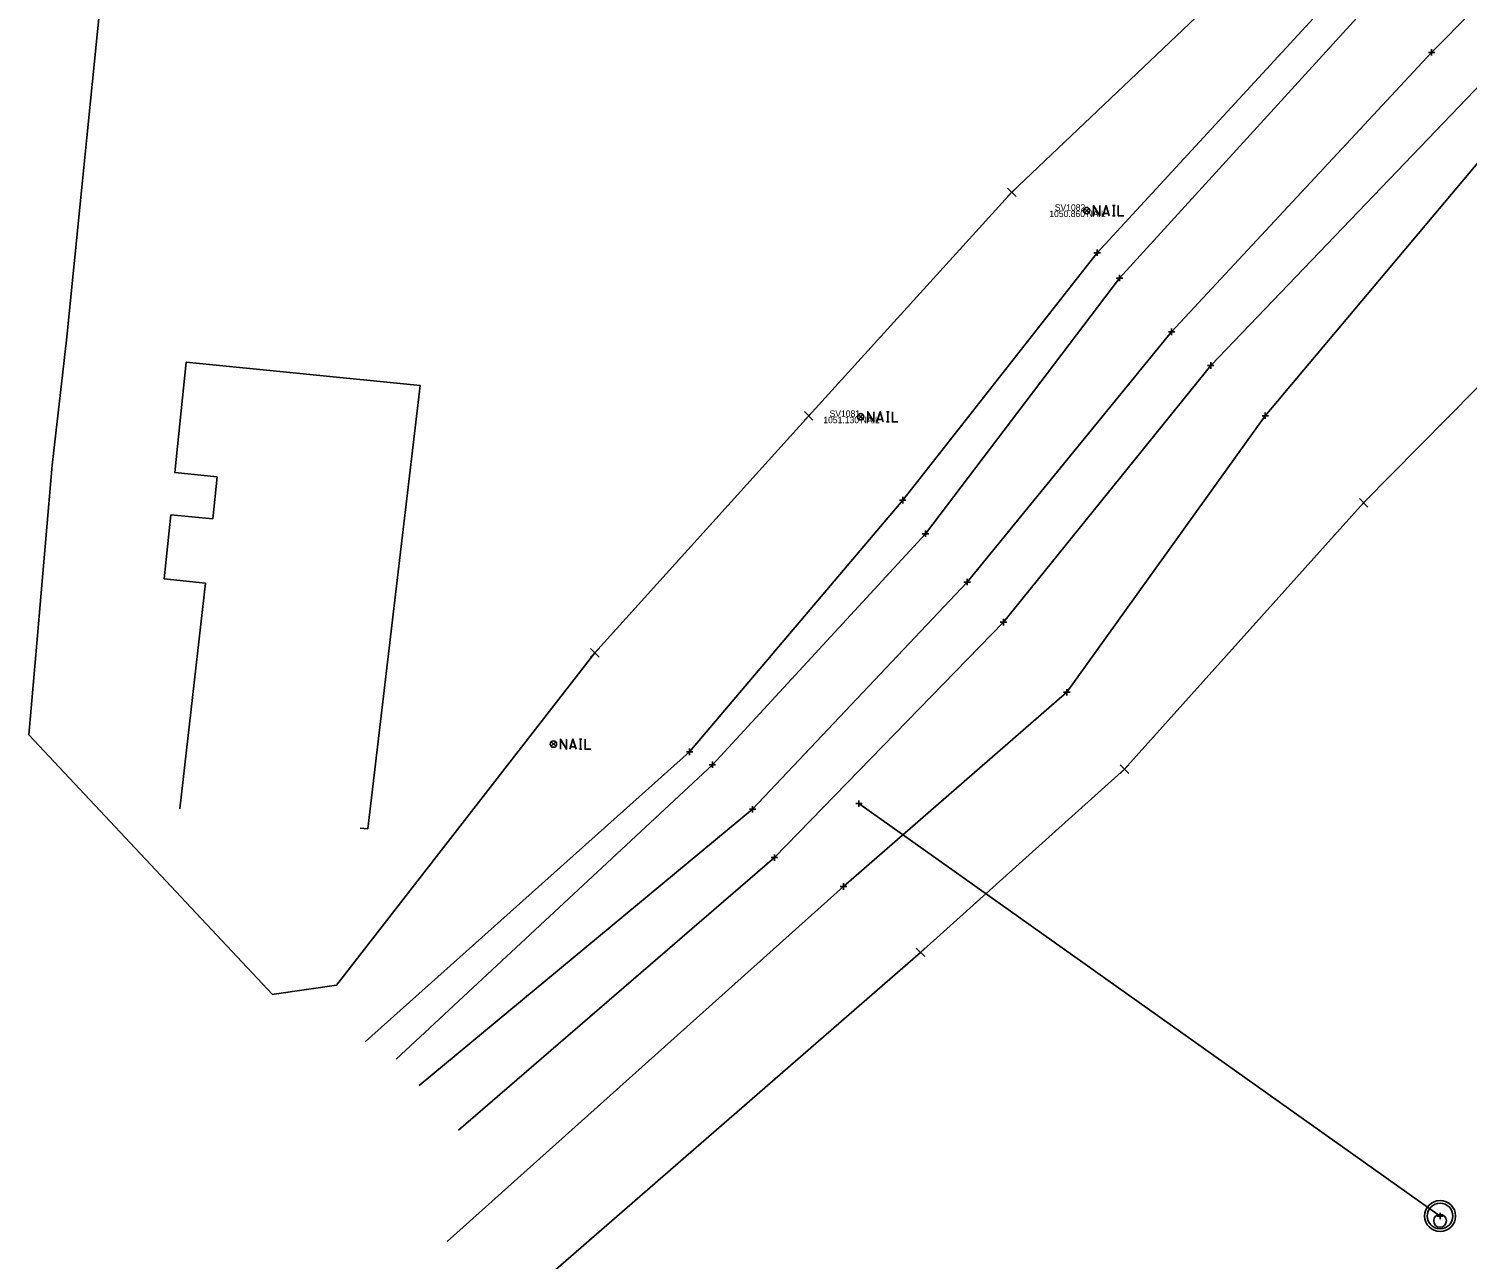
# Model space of a CAD drawing. Extents: x 1620404 to 1621386, y 607070 to 607748.
# Drawn here: x 1620985.2 to 1621209.9, y 607390.4 to 607582.5 of the extents above; entities that cross this region are included whole.
import ezdxf

# ---------------------------------------------------------------- set-up
doc = ezdxf.new("R2010")
doc.units = 0
for name, color, linetype in [('BD_X_Building', 7, 'Continuous'), ('BD_X_Porch_or_Deck', 7, 'Continuous'), ('Default', 7, 'Continuous'), ('DR_X_Cells', 7, 'Continuous'), ('DR_X_Elev_Flow', 7, 'Continuous'), ('PM_X_Cells', 7, 'Continuous'), ('PV_X_Curb', 7, 'Continuous'), ('SN_X_Public', 7, 'Continuous'), ('SV_P_Control_Cells_Set', 7, 'Continuous'), ('SV_X_Shot_Marker', 7, 'Continuous'), ('UT_X_Gas_Cells', 7, 'Continuous'), ('UT_X_Sanitary_Cells', 7, 'Continuous'), ('UT_X_Sanitary_Line', 7, 'Continuous'), ('UT_X_Water', 7, 'Continuous'), ('UT_X_Water_Cells', 7, 'Continuous'), ('VG_X_Cells', 7, 'Continuous')]:
    doc.layers.add(name, color=color, linetype=linetype)

msp = doc.modelspace()

# ---------------------------------------------------------------- linework, layer by layer
at = {"layer": 'BD_X_Porch_or_Deck'}
msp.add_line((1621114.88, 607461.49), (1621205.63, 607397.11), dxfattribs=at)
at = {"layer": 'Default'}
for points in [[(1621181.91, 607597.97), (1621138.75, 607556.94), (1621107.03, 607522.04), (1621073.63, 607485.02), (1621033.29, 607433.17), (1621023.55, 607431.72), (1621023.3, 607431.68), (1620985.23, 607472.25), (1620986.35, 607484.73), (1620988.88, 607514.33), (1620991.13, 607533.86), (1620993.6, 607558.73), (1620994.28, 607565.51), (1620996.79, 607590.39)], [(1621054.39, 607377.32), (1621124.5, 607438.27), (1621156.33, 607466.87), (1621193.69, 607508.45), (1621263.9, 607579.48)]]:
    msp.add_lwpolyline(points, dxfattribs=at)
at = {"layer": 'DR_X_Cells'}
for p, q in [((1621114.38, 607461.49), (1621115.38, 607461.49)), ((1621114.88, 607461.99), (1621114.88, 607460.99)), ((1621114.88, 607461.49), (1621114.88, 607461.49)), ((1621205.13, 607397.11), (1621206.13, 607397.11)), ((1621205.63, 607397.61), (1621205.63, 607396.61)), ((1621205.63, 607397.11), (1621205.63, 607397.11))]:
    msp.add_line(p, q, dxfattribs=at)
at = {"layer": 'DR_X_Elev_Flow'}
for p, q in [((1621150.09, 607554.43), (1621150.79, 607553.73)), ((1621150.09, 607553.73), (1621150.79, 607554.43)), ((1621114.8, 607522.24), (1621115.5, 607521.54)), ((1621114.8, 607521.54), (1621115.5, 607522.24)), ((1621066.82, 607471.14), (1621067.52, 607470.44)), ((1621066.82, 607470.44), (1621067.52, 607471.14))]:
    msp.add_line(p, q, dxfattribs=at)
for points in [[(1621151.53, 607553.27), (1621151.53, 607554.87), (1621152.47, 607553.27), (1621152.47, 607554.87)], [(1621152.98, 607553.27), (1621153.48, 607554.87), (1621153.97, 607553.27)], [(1621154.48, 607554.87), (1621154.88, 607554.87)], [(1621154.68, 607553.27), (1621154.68, 607554.87)], [(1621155.38, 607554.87), (1621155.38, 607553.27), (1621156.25, 607553.27)], [(1621153.85, 607553.65), (1621153.1, 607553.65)], [(1621154.48, 607553.27), (1621154.88, 607553.27)], [(1621116.24, 607521.08), (1621116.24, 607522.68), (1621117.18, 607521.08), (1621117.18, 607522.68)], [(1621117.69, 607521.08), (1621118.19, 607522.68), (1621118.68, 607521.08)], [(1621119.19, 607522.68), (1621119.59, 607522.68)], [(1621119.39, 607521.08), (1621119.39, 607522.68)], [(1621120.09, 607522.68), (1621120.09, 607521.08), (1621120.96, 607521.08)], [(1621118.56, 607521.46), (1621117.81, 607521.46)], [(1621119.19, 607521.08), (1621119.59, 607521.08)], [(1621068.26, 607469.98), (1621068.26, 607471.58), (1621069.2, 607469.98), (1621069.2, 607471.58)], [(1621069.71, 607469.98), (1621070.21, 607471.58), (1621070.7, 607469.98)], [(1621071.21, 607471.58), (1621071.61, 607471.58)], [(1621071.41, 607469.98), (1621071.41, 607471.58)], [(1621072.11, 607471.58), (1621072.11, 607469.98), (1621072.98, 607469.98)], [(1621070.58, 607470.36), (1621069.83, 607470.36)], [(1621071.21, 607469.98), (1621071.61, 607469.98)]]:
    msp.add_lwpolyline(points, dxfattribs=at)
for centre in [(1621150.44, 607554.08), (1621115.15, 607521.89), (1621067.17, 607470.79)]:
    msp.add_circle(centre, 0.5, dxfattribs=at)
at = {"layer": 'PM_X_Cells'}
for centre, radius in [((1621205.63, 607397.11), 2.42), ((1621205.63, 607397.11), 2), ((1621205.63, 607396.36), 1)]:
    msp.add_circle(centre, radius, dxfattribs=at)
at = {"layer": 'PV_X_Curb'}
msp.add_lwpolyline([(1621098.26, 607460.62), (1621131.78, 607496.09), (1621163.7, 607535.15), (1621204.3, 607578.78), (1621236.39, 607611.18), (1621277.1, 607640.63), (1621316.81, 607671.58), (1621364.8, 607706.19)], dxfattribs=at)
at = {"layer": 'SN_X_Public'}
for p, q in [((1621204.3, 607579.28), (1621204.3, 607578.28)), ((1621203.8, 607578.78), (1621204.8, 607578.78)), ((1621204.3, 607578.78), (1621204.3, 607578.78)), ((1621151.58, 607547.5), (1621152.58, 607547.5)), ((1621152.08, 607548), (1621152.08, 607547)), ((1621152.08, 607547.5), (1621152.08, 607547.5)), ((1621155.07, 607543.55), (1621156.07, 607543.55)), ((1621155.57, 607544.05), (1621155.57, 607543.05)), ((1621155.57, 607543.55), (1621155.57, 607543.55)), ((1621163.2, 607535.15), (1621164.2, 607535.15)), ((1621163.7, 607535.65), (1621163.7, 607534.65)), ((1621163.7, 607535.15), (1621163.7, 607535.15)), ((1621169.31, 607529.9), (1621170.31, 607529.9)), ((1621169.81, 607530.4), (1621169.81, 607529.4)), ((1621169.81, 607529.9), (1621169.81, 607529.9)), ((1621177.82, 607522.05), (1621178.82, 607522.05)), ((1621178.32, 607522.55), (1621178.32, 607521.55)), ((1621178.32, 607522.05), (1621178.32, 607522.05)), ((1621121.71, 607509.37), (1621121.71, 607508.37)), ((1621121.21, 607508.87), (1621122.21, 607508.87)), ((1621121.71, 607508.87), (1621121.71, 607508.87)), ((1621124.77, 607503.64), (1621125.77, 607503.64)), ((1621125.27, 607504.14), (1621125.27, 607503.14)), ((1621125.27, 607503.64), (1621125.27, 607503.64)), ((1621131.28, 607496.09), (1621132.28, 607496.09)), ((1621131.78, 607496.59), (1621131.78, 607495.59)), ((1621131.78, 607496.09), (1621131.78, 607496.09)), ((1621136.95, 607489.83), (1621137.95, 607489.83)), ((1621137.45, 607490.33), (1621137.45, 607489.33)), ((1621137.45, 607489.83), (1621137.45, 607489.83)), ((1621146.84, 607478.88), (1621147.84, 607478.88)), ((1621147.34, 607479.38), (1621147.34, 607478.38)), ((1621147.34, 607478.88), (1621147.34, 607478.88)), ((1621087.92, 607469.58), (1621088.92, 607469.58)), ((1621088.42, 607470.08), (1621088.42, 607469.08)), ((1621088.42, 607469.58), (1621088.42, 607469.58)), ((1621091.48, 607467.57), (1621092.48, 607467.57)), ((1621091.98, 607468.07), (1621091.98, 607467.07)), ((1621091.98, 607467.57), (1621091.98, 607467.57)), ((1621097.76, 607460.62), (1621098.76, 607460.62)), ((1621098.26, 607461.12), (1621098.26, 607460.12)), ((1621098.26, 607460.62), (1621098.26, 607460.62)), ((1621101.17, 607453.07), (1621102.17, 607453.07)), ((1621101.67, 607453.57), (1621101.67, 607452.57)), ((1621101.67, 607453.07), (1621101.67, 607453.07)), ((1621111.96, 607448.56), (1621112.96, 607448.56)), ((1621112.46, 607449.06), (1621112.46, 607448.06)), ((1621112.46, 607448.56), (1621112.46, 607448.56))]:
    msp.add_line(p, q, dxfattribs=at)
at = {"layer": 'SV_X_Shot_Marker'}
for p, q in [((1621138.08, 607556.27), (1621139.42, 607557.61)), ((1621138.08, 607557.61), (1621139.42, 607556.27)), ((1621106.36, 607521.37), (1621107.7, 607522.71)), ((1621106.36, 607522.71), (1621107.7, 607521.37)), ((1621193.02, 607507.78), (1621194.36, 607509.12)), ((1621193.02, 607509.12), (1621194.36, 607507.78)), ((1621072.96, 607484.35), (1621074.3, 607485.69)), ((1621072.96, 607485.69), (1621074.3, 607484.35)), ((1621155.66, 607466.2), (1621157, 607467.54)), ((1621155.66, 607467.54), (1621157, 607466.2)), ((1621123.83, 607437.6), (1621125.17, 607438.94)), ((1621123.83, 607438.94), (1621125.17, 607437.6))]:
    msp.add_line(p, q, dxfattribs=at)
at = {"layer": 'UT_X_Gas_Cells'}
for points in [[(1621088.42, 607469.58), (1621121.71, 607508.87), (1621152.08, 607547.5), (1621190.16, 607588.87), (1621224.62, 607622.05), (1621265.66, 607652.5), (1621309.41, 607687.37), (1621352.88, 607724.24)], [(1621112.46, 607448.56), (1621147.34, 607478.88), (1621178.32, 607522.05), (1621214.26, 607564.83), (1621247.99, 607596.27), (1621328.73, 607656.81), (1621371.23, 607684.72)]]:
    msp.add_lwpolyline(points, dxfattribs=at)
at = {"layer": 'UT_X_Sanitary_Cells'}
for points in [[(1621091.98, 607467.57), (1621125.27, 607503.64), (1621155.57, 607543.55), (1621194.23, 607585.96), (1621229.27, 607619.63), (1621270.17, 607649.45), (1621313.41, 607682.02), (1621357.67, 607717.03)], [(1621101.67, 607453.07), (1621137.45, 607489.83), (1621169.81, 607529.9), (1621212.19, 607574.07), (1621242.36, 607603.23), (1621282.59, 607631.86), (1621321.56, 607662.92), (1621368.83, 607693.52)]]:
    msp.add_lwpolyline(points, dxfattribs=at)
at = {"layer": 'UT_X_Sanitary_Line'}
for p, q in [((1621008.06, 607513.17), (1621009.8, 607530.43)), ((1621009.8, 607530.43), (1621046.34, 607526.76)), ((1621046.34, 607526.76), (1621038.17, 607457.56)), ((1621014.64, 607512.51), (1621008.06, 607513.17)), ((1621013.98, 607505.94), (1621014.64, 607512.51)), ((1621006.4, 607496.57), (1621007.4, 607506.6)), ((1621007.4, 607506.6), (1621013.98, 607505.94)), ((1621012.81, 607495.92), (1621006.4, 607496.57)), ((1621008.8, 607460.67), (1621012.81, 607495.92)), ((1621036.98, 607457.68), (1621038.17, 607457.56))]:
    msp.add_line(p, q, dxfattribs=at)
at = {"layer": 'UT_X_Water_Cells'}
for p, q in [((1621205.63, 607399.11), (1621205.63, 607399.11)), ((1621205.63, 607397.11), (1621205.63, 607397.11)), ((1621205.63, 607397.11), (1621205.63, 607397.11)), ((1621205.63, 607396.36), (1621205.63, 607396.36)), ((1621205.63, 607395.11), (1621205.63, 607395.11))]:
    msp.add_line(p, q, dxfattribs=at)
msp.add_circle((1621205.63, 607397.11), 2, dxfattribs=at)
at = {"layer": 'VG_X_Cells'}
for p, q in [((1621037.83, 607424.33), (1621088.42, 607469.58)), ((1621091.98, 607467.57), (1621042.62, 607421.61)), ((1621046.19, 607417.46), (1621098.26, 607460.62)), ((1621101.67, 607453.07), (1621052.34, 607410.52)), ((1621112.46, 607448.56), (1621050.59, 607393.13))]:
    msp.add_line(p, q, dxfattribs=at)

# ---------------------------------------------------------------- texts
at = {"layer": 'BD_X_Building'}
for p in [(1621150.44, 607553.08), (1621115.15, 607520.89)]:
    msp.add_text('NAIL', height=1, dxfattribs=at).set_placement(p)
at = {"layer": 'SV_P_Control_Cells_Set'}
for s, p in [('SV1082', (1621145.46, 607554.08)), ('SV1081', (1621110.29, 607521.89))]:
    msp.add_text(s, height=1, dxfattribs=at).set_placement(p)
at = {"layer": 'UT_X_Water'}
for s, p in [('1050.860', (1621144.6, 607553.08)), ('1051.130', (1621109.31, 607520.89))]:
    msp.add_text(s, height=1, dxfattribs=at).set_placement(p)

doc.saveas('drawing.dxf')
